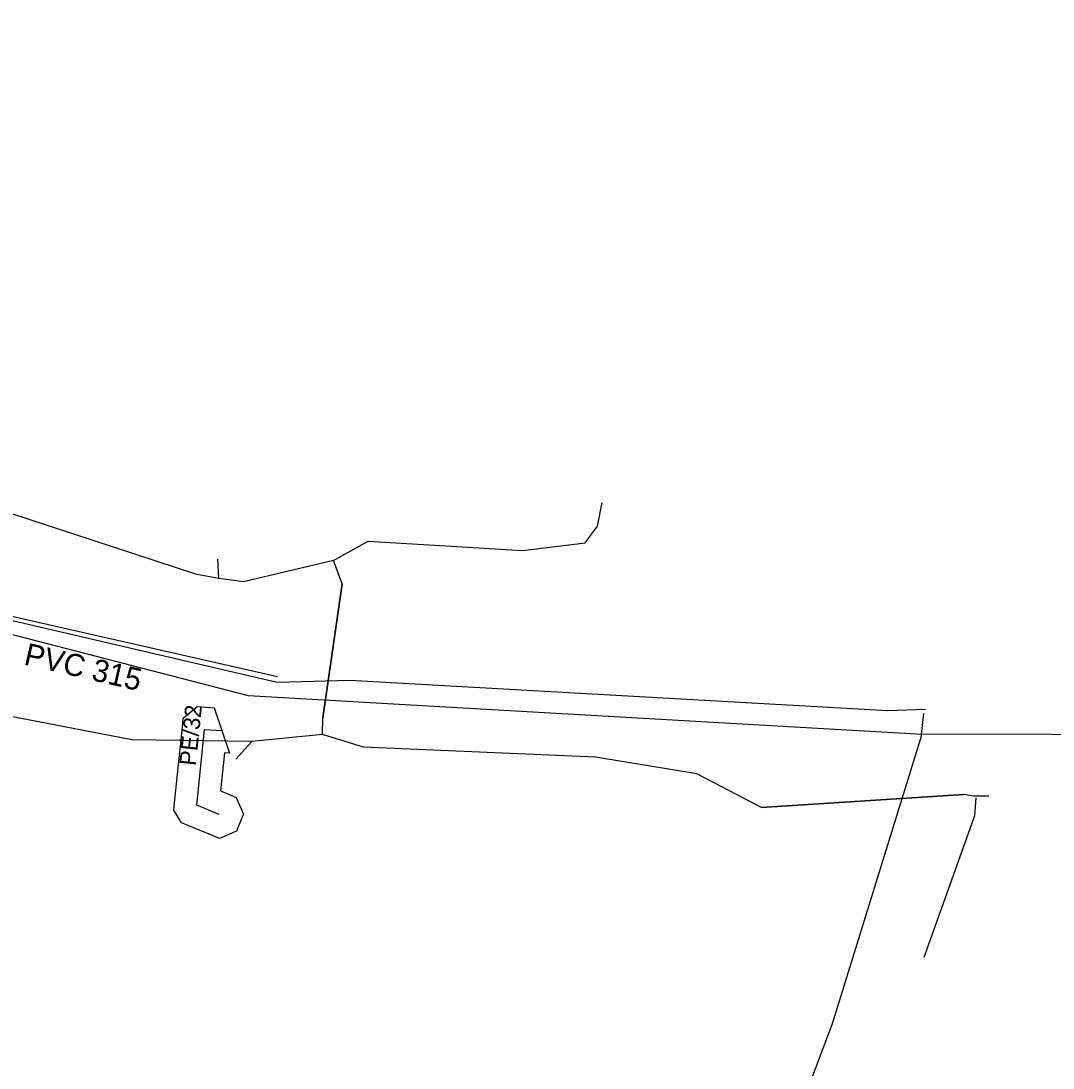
# Model space of a CAD drawing. Extents: x -743072 to -742584, y -978827 to -978325.
# Drawn here: x -742747.25 to -742700.74, y -978636.51 to -978589.34 of the extents above; entities that cross this region are included whole.
import ezdxf

# ---------------------------------------------------------------- set-up
doc = ezdxf.new("R2010")
doc.units = 0
for name, color, linetype in [('IS_CETIN_sdělovací kabel_optika', 7, 'Continuous'), ('IS_GasNet_ochr pasmo', 7, 'Continuous'), ('IS_GasNet_plyn STL', 7, 'Continuous'), ('IS_popis_GasNet', 7, 'Continuous'), ('IS_popis_ScVK', 7, 'Continuous'), ('IS_ScVK_Kanal_dest', 7, 'Continuous'), ('IS_ScVK_Kanal_spl', 7, 'Continuous'), ('IS_ScVK_Vodovod', 7, 'Continuous')]:
    doc.layers.add(name, color=color, linetype=linetype)

msp = doc.modelspace()

# ---------------------------------------------------------------- linework, layer by layer
at = {"layer": 'IS_CETIN_sdělovací kabel_optika'}
for points in [[(-742739.33, -978614.28), (-742747.75, -978611.52), (-742748.84, -978610.49), (-742750.19, -978610.45), (-742758.62, -978606.87), (-742764.74, -978604.1)], [(-742721.27, -978612.1), (-742721.06, -978611.03)], [(-742733.16, -978613.65), (-742731.6, -978612.78), (-742724.63, -978613.2), (-742721.82, -978612.85), (-742721.27, -978612.1)], [(-742738.33, -978614.45), (-742738.384, -978613.588)], [(-742733.16, -978613.65), (-742737.22, -978614.6), (-742738.33, -978614.45)], [(-742733.66, -978621.49), (-742733.65, -978620.73), (-742732.77, -978614.7), (-742733.16, -978613.65)], [(-742738.33, -978614.45), (-742739.33, -978614.28)], [(-742732.77, -978614.7), (-742733.65, -978620.73)], [(-742736.84, -978621.8), (-742742.25, -978621.73), (-742749.51, -978620.32), (-742755.96, -978617.33)], [(-742736.84, -978621.8), (-742737.57, -978622.6)], [(-742733.66, -978621.49), (-742736.84, -978621.8)], [(-742703.63, -978624.26), (-742704.3, -978624.26), (-742704.76, -978624.19), (-742713.88, -978624.77), (-742716.79, -978623.25), (-742721.36, -978622.5), (-742731.81, -978622.06), (-742733.66, -978621.49)], [(-742713.88, -978624.77), (-742704.76, -978624.19)], [(-742704.22, -978624.34), (-742704.27, -978625.14), (-742706.56, -978631.52)]]:
    msp.add_lwpolyline(points, dxfattribs=at)
at = {"layer": 'IS_GasNet_ochr pasmo'}
msp.add_lwpolyline([(-742738.539, -978620.277), (-742737.855, -978622.327), (-742738.084, -978622.312), (-742738.259, -978624.02), (-742737.929, -978624.155), (-742737.546, -978624.313), (-742737.228, -978625.078), (-742737.385, -978625.461), (-742737.543, -978625.844), (-742738.308, -978626.162), (-742738.691, -978626.005), (-742739.711, -978625.585), (-742740.018, -978625.458), (-742740.359, -978624.888), (-742740.325, -978624.558), (-742739.975, -978621.148), (-742739.934, -978620.746), (-742739.316, -978620.225), (-742738.913, -978620.252)], close=True, dxfattribs=at)
at = {"layer": 'IS_GasNet_plyn STL'}
msp.add_lwpolyline([(-742738.31, -978625.08), (-742739.33, -978624.66), (-742738.98, -978621.25), (-742738.197, -978621.302)], dxfattribs=at)
at = {"layer": 'IS_ScVK_Kanal_dest'}
msp.add_lwpolyline([(-742836.89, -978635.23), (-742836.829, -978632.584), (-742794.674, -978604.136), (-742784.548, -978596.4), (-742778.303, -978601.806), (-742769.218, -978607.658), (-742757.236, -978613.629), (-742748.697, -978616.71), (-742737.016, -978619.72), (-742706.897, -978621.455), (-742694.704, -978621.477), (-742669.125, -978621.524), (-742647.601, -978624.622), (-742643.224, -978625.196), (-742627.191, -978628.893), (-742614.992, -978632.031), (-742608.58, -978633.224), (-742593.026, -978634.809), (-742583.863, -978635.543)], dxfattribs=at)
at = {"layer": 'IS_ScVK_Kanal_spl'}
msp.add_lwpolyline([(-742735.694, -978618.888), (-742750.925, -978615.432)], dxfattribs=at)
at = {"layer": 'IS_ScVK_Vodovod'}
for points in [[(-742784.881, -978589.342), (-742782.914, -978591.311), (-742778.041, -978596.473), (-742774.837, -978604.776), (-742757.802, -978612.539), (-742750.675, -978615.636), (-742735.708, -978619.127), (-742732.432, -978619.039), (-742708.184, -978620.401), (-742706.491, -978620.342)], [(-742706.569, -978620.537), (-742706.695, -978621.62), (-742710.69, -978634.52), (-742715.539, -978647.389), (-742724.81, -978661.243), (-742734.894, -978676.393), (-742735.409, -978677.167), (-742737.884, -978680.886)]]:
    msp.add_lwpolyline(points, dxfattribs=at)

# ---------------------------------------------------------------- texts
at = {"layer": 'IS_popis_GasNet'}
msp.add_text('PE/32', height=0.75, rotation=84.1397, dxfattribs=at).set_placement((-742739.371, -978622.913))
at = {"layer": 'IS_popis_ScVK'}
msp.add_text('PVC 315 ', height=1, rotation=347, dxfattribs=at).set_placement((-742747.161, -978618.322))

doc.saveas('drawing.dxf')
